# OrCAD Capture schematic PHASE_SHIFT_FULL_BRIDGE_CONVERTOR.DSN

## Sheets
1 PAGE2: size A
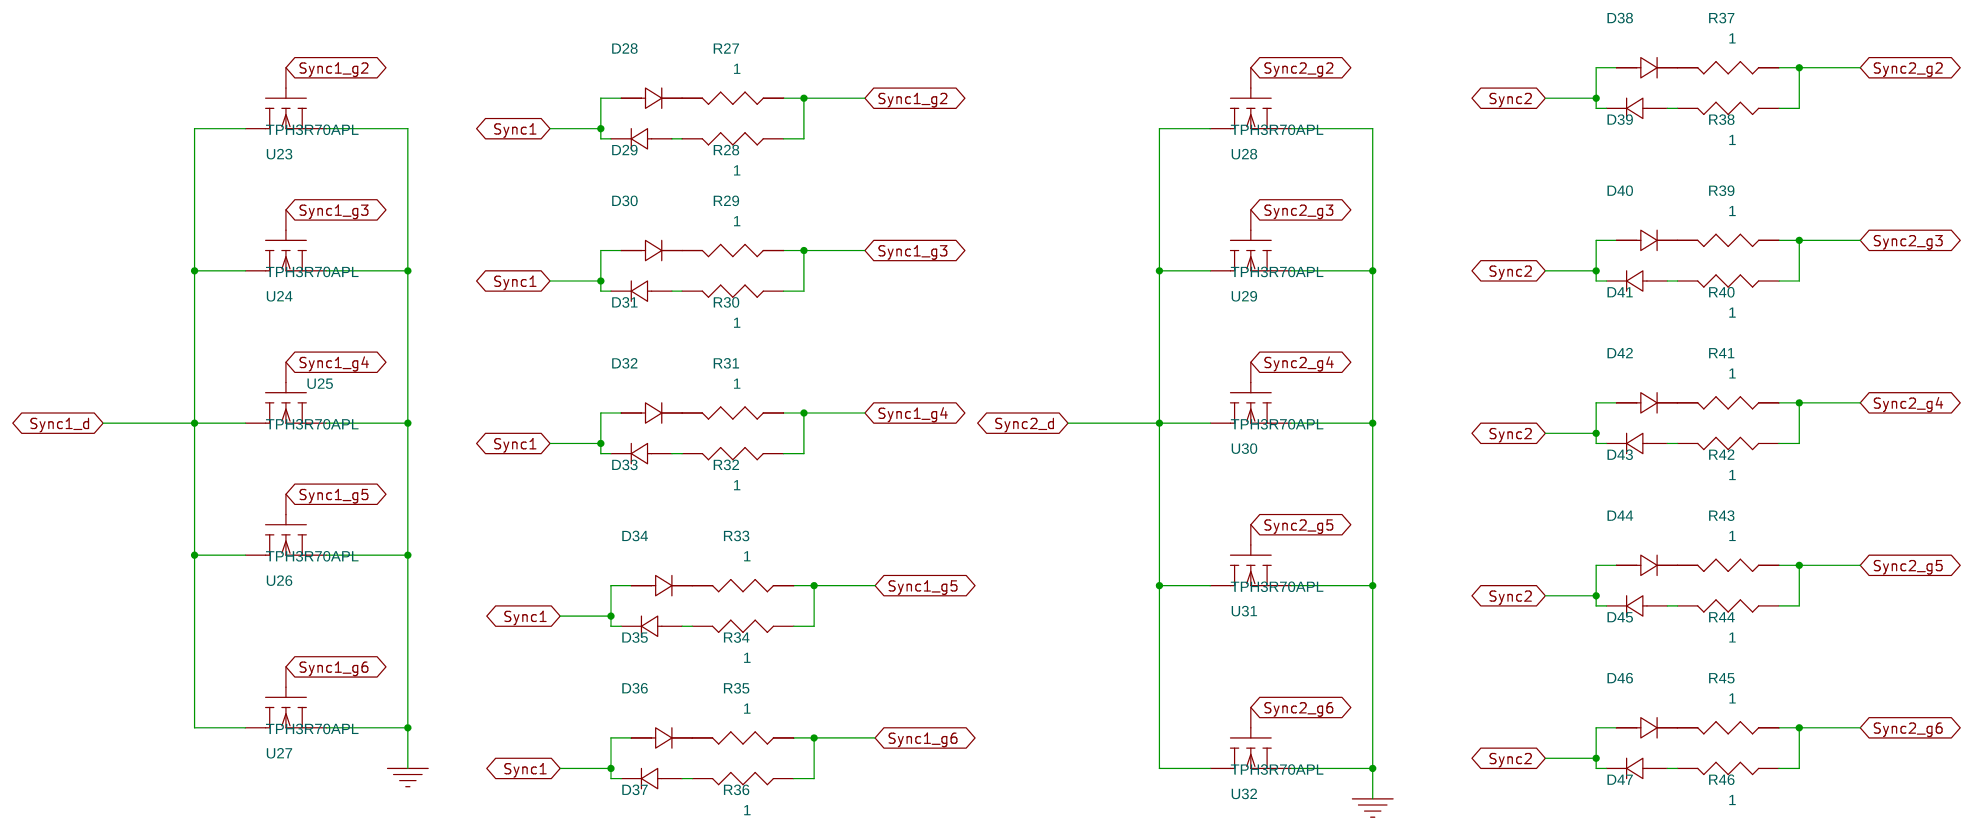
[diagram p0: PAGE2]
2 PAGE1: size A
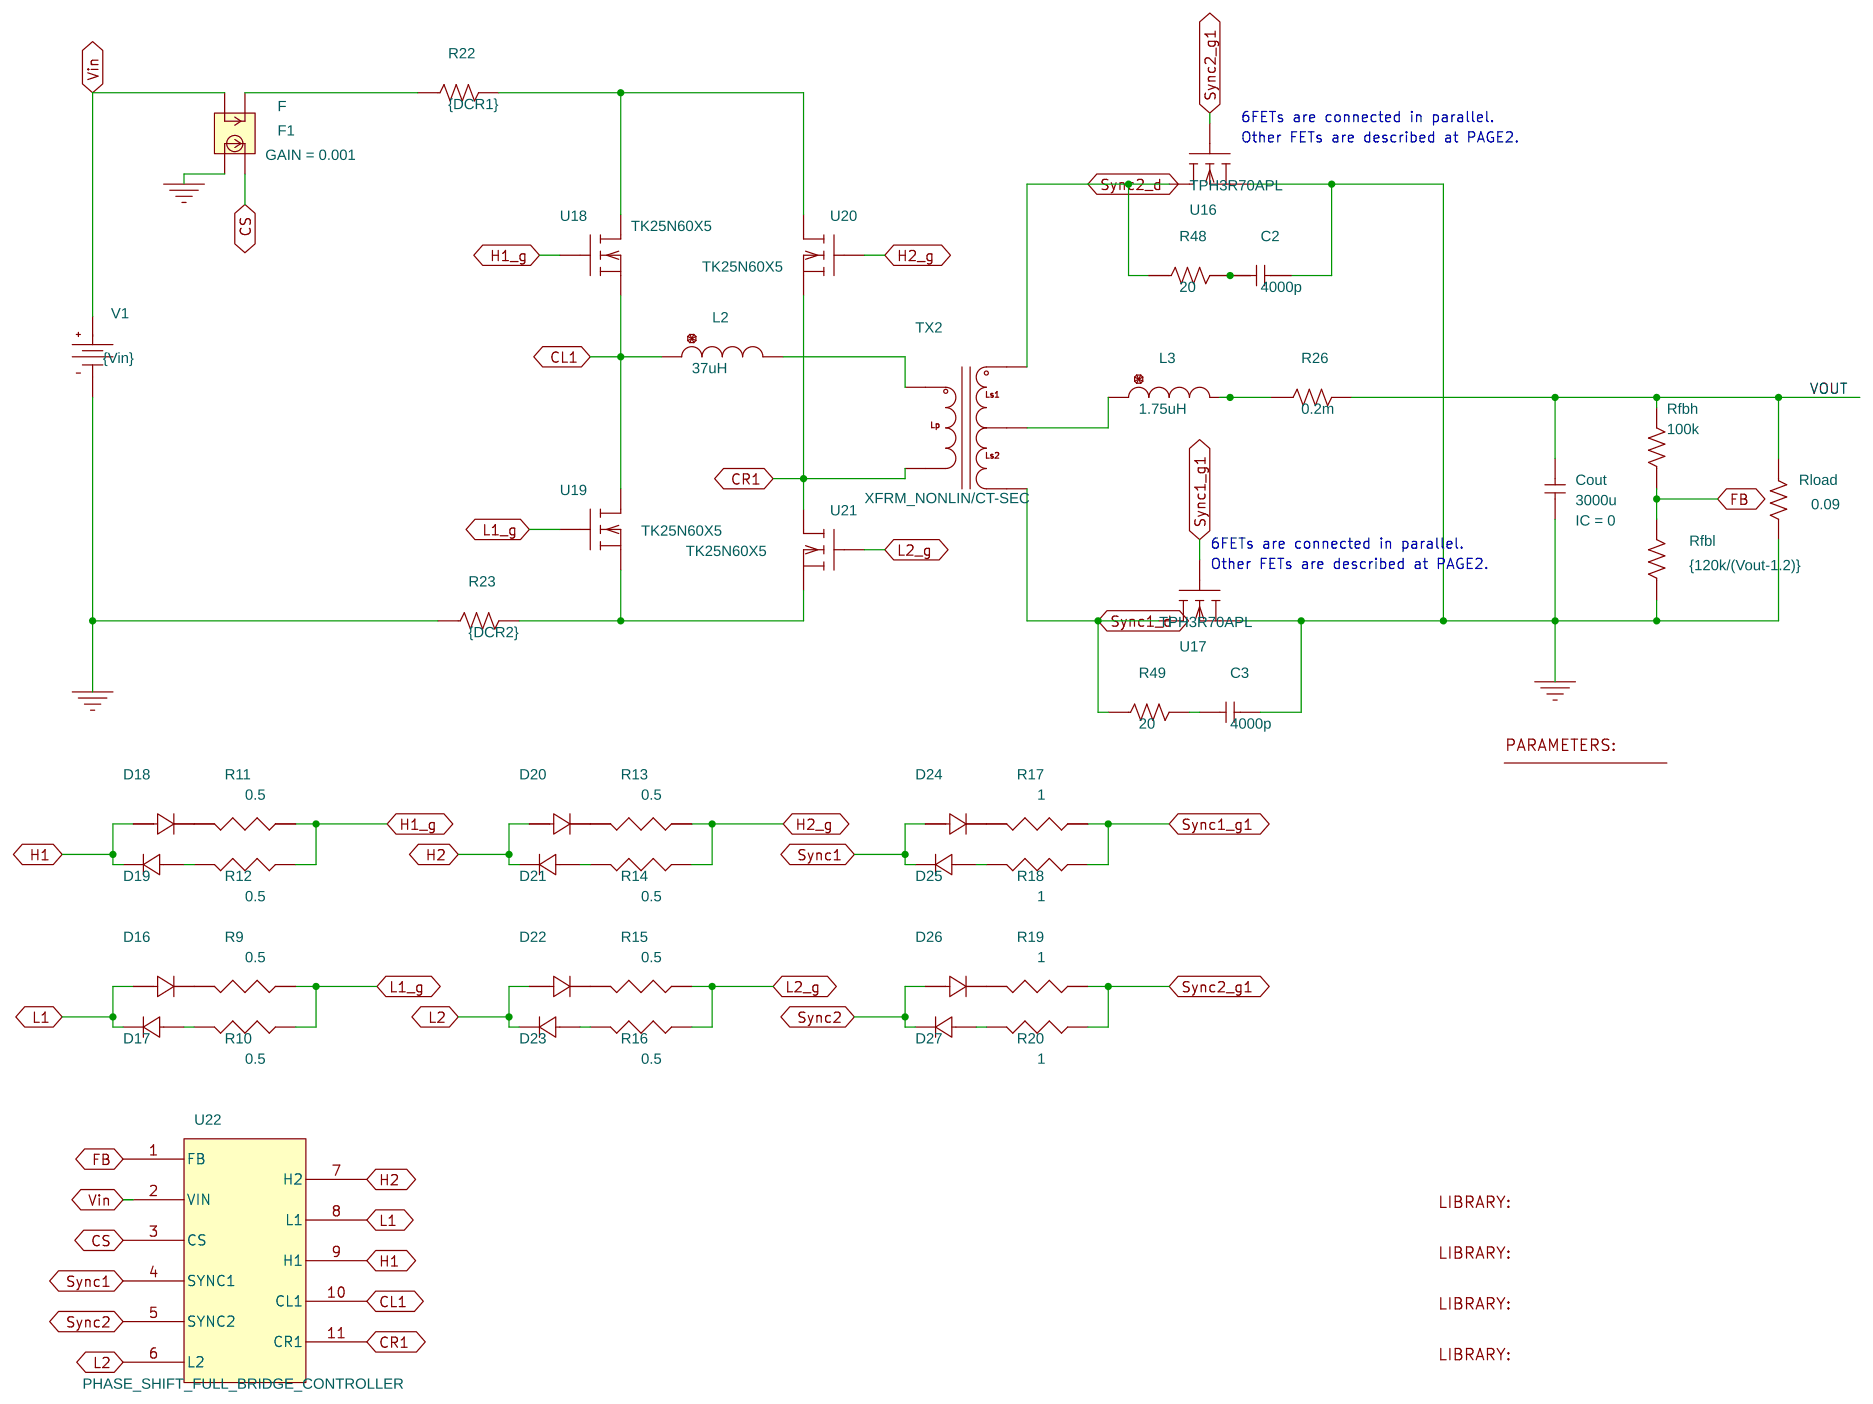
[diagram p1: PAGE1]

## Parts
sheet PAGE1
1  PARAM
C2  4000p  [cap196]
C3  4000p  [cap196]
Cout  3000u  [RAD/CK05]
D16  Diode_nom
D17  Diode_nom
D18  Diode_nom
D19  Diode_nom
D20  Diode_nom
D21  Diode_nom
D22  Diode_nom
D23  Diode_nom
D24  Diode_nom
D25  Diode_nom
D26  Diode_nom
D27  Diode_nom
F1  F
L2  37uH  [DISC350x175LS200x100034]
L3  1.75uH  [DISC350x175LS200x100034]
LIB1  LIB
LIB2  LIB
LIB3  LIB
LIB4  LIB
R9  0.5  [AXRC05]
R10  0.5  [AXRC05]
R11  0.5  [AXRC05]
R12  0.5  [AXRC05]
R13  0.5  [AXRC05]
R14  0.5  [AXRC05]
R15  0.5  [AXRC05]
R16  0.5  [AXRC05]
R17  1  [AXRC05]
R18  1  [AXRC05]
R19  1  [AXRC05]
R20  1  [AXRC05]
R22  {DCR1}  [AXRC05]
R23  {DCR2}  [AXRC05]
R26  0.2m  [AXRC05]
R48  20  [AXRC05]
R49  20  [AXRC05]
Rfbh  100k  [AXRC05]
Rfbl  {120k/(Vout-1.2)}  [AXRC05]
Rload  0.09  [AX/RC05]
TX2  XFRM_NONLIN/CT-SEC
U16  TPH3R70APL
U17  TPH3R70APL
U18  TK25N60X5
U19  TK25N60X5
U20  TK25N60X5
U21  TK25N60X5
U22  PHASE_SHIFT_FULL_BRIDGE_CONTROLLER
V1  VDC
sheet PAGE2
D28  Diode_nom
D29  Diode_nom
D30  Diode_nom
D31  Diode_nom
D32  Diode_nom
D33  Diode_nom
D34  Diode_nom
D35  Diode_nom
D36  Diode_nom
D37  Diode_nom
D38  Diode_nom
D39  Diode_nom
D40  Diode_nom
D41  Diode_nom
D42  Diode_nom
D43  Diode_nom
D44  Diode_nom
D45  Diode_nom
D46  Diode_nom
D47  Diode_nom
R27  1  [AXRC05]
R28  1  [AXRC05]
R29  1  [AXRC05]
R30  1  [AXRC05]
R31  1  [AXRC05]
R32  1  [AXRC05]
R33  1  [AXRC05]
R34  1  [AXRC05]
R35  1  [AXRC05]
R36  1  [AXRC05]
R37  1  [AXRC05]
R38  1  [AXRC05]
R39  1  [AXRC05]
R40  1  [AXRC05]
R41  1  [AXRC05]
R42  1  [AXRC05]
R43  1  [AXRC05]
R44  1  [AXRC05]
R45  1  [AXRC05]
R46  1  [AXRC05]
U23  TPH3R70APL
U24  TPH3R70APL
U25  TPH3R70APL
U26  TPH3R70APL
U27  TPH3R70APL
U28  TPH3R70APL
U29  TPH3R70APL
U30  TPH3R70APL
U31  TPH3R70APL
U32  TPH3R70APL

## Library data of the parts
1 = PARAM: DCR1: 5m; DCR2: 5m; Fc: 120k; Rdrv_off_p: 1.0; Rdrv_off_s: 0.5; Rdrv_on_p: 5.3; Rdrv_on_s: 5; Tdl: 300n; Tdr: 300n; Vdrv_H_p: 12; Vdrv_H_s: 12; Vin: 380; Vout: 12
C2 C3 = C
Cout = C_2: IC: 0
D16-D47 = Diode_nom
F1 = F: GAIN: 0.001
L2 L3 = L
LIB1 = LIB: FILENAME: ../../../Lib/TK25N60X5.lib
LIB2 = LIB: FILENAME: ../../../Lib/TPH3R70APL.lib
LIB3 = LIB: FILENAME: ../../../Lib/diode_nom.lib
LIB4 = LIB: FILENAME: ../../../lib/Phase_shift_controller.lib
R9-R20 R27-R46 = R
R22 R23 R26 R48 R49 Rfbh Rfbl Rload = R_v2
TX2 = XFRM_NONLIN_CT-SEC: COUPLING: 1; LP_TURNS: 400; LS1_TURNS: 20; LS2_TURNS: 20; RP_VALUE: 75e-3; RS_VALUE: 0.25e-3
U16 U17 U23-U32 = TPH3R70APL
U18-U21 = TK25N60X5
U22 = PHASE_SHIFT_FULL_BRIDGE_CONTROL
V1 = VDC: DC: {Vin}

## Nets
Vin: F1.1 U22.2(VIN) V1.0(+)
0: C2.2 C3.2 Cout.2 F1.3 R23.1 Rfbl.1 Rload.2 U16.0(s) U17.0(s) U23.0(s) U24.0(s) U25.0(s) U26.0(s) U27.0(s) U28.0(s) U29.0(s) U30.0(s) U31.0(s) U32.0(s) V1.1(-)
CL1: L2.1 U18.0(s) U19.2(d) U22.10(CL1)
CR1: TX2.1(3) U20.0(s) U21.2(d) U22.11(CR1)
CS: F1.4 U22.3(CS)
FB: Rfbh.1 Rfbl.2 U22.1(FB)
H1: D18.0(1) D19.1(2) U22.9(H1)
H1_g: R11.1 R12.1 U18.1(g)
H2: D20.0(1) D21.1(2) U22.7(H2)
H2_g: R13.1 R14.1 U20.1(g)
L1: D16.0(1) D17.1(2) U22.8(L1)
L1_g: R9.1 R10.1 U19.1(g)
L2: D22.0(1) D23.1(2) U22.6(L2)
L2_g: R15.1 R16.1 U21.1(g)
Sync1: D24.0(1) D25.1(2) D28.0(1) D29.1(2) D30.0(1) D31.1(2) D32.0(1) D33.1(2) D34.0(1) D35.1(2) D36.0(1) D37.1(2) U22.4(SYNC1)
Sync1_d: R49.1 TX2.4(6) U17.2(d) U23.2(d) U24.2(d) U25.2(d) U26.2(d) U27.2(d)
Sync1_g1: R17.1 R18.1 U17.1(g)
Sync1_g2: R27.1 R28.1 U23.1(g)
Sync1_g3: R29.1 R30.1 U24.1(g)
Sync1_g4: R31.1 R32.1 U25.1(g)
Sync1_g5: R33.1 R34.1 U26.1(g)
Sync1_g6: R35.1 R36.1 U27.1(g)
Sync2: D26.0(1) D27.1(2) D38.0(1) D39.1(2) D40.0(1) D41.1(2) D42.0(1) D43.1(2) D44.0(1) D45.1(2) D46.0(1) D47.1(2) U22.5(SYNC2)
Sync2_d: R48.1 TX2.2(4) U16.2(d) U28.2(d) U29.2(d) U30.2(d) U31.2(d) U32.2(d)
Sync2_g1: R19.1 R20.1 U16.1(g)
Sync2_g2: R37.1 R38.1 U28.1(g)
Sync2_g3: R39.1 R40.1 U29.1(g)
Sync2_g4: R41.1 R42.1 U30.1(g)
Sync2_g5: R43.1 R44.1 U31.1(g)
Sync2_g6: R45.1 R46.1 U32.1(g)
VOUT: Cout.1 R26.2 Rfbh.2 Rload.1
N2254419: F1.2 R22.1
N2254423: R22.2 U18.2(d) U20.2(d)
N2254655: L2.2 TX2.0(1)
N2254721: L3.1 TX2.3(5)
N2254725: L3.2 R26.1
N2254961: R23.2 U19.0(s) U21.0(s)
N2255439: D25.0(1) R18.2
N2255467: D19.0(1) R12.2
N2255537: D21.0(1) R14.2
N2255895: D27.0(1) R20.2
N2255923: D17.0(1) R10.2
N2255993: D23.0(1) R16.2
N2258498: D26.1(2) R19.2
N2258518: D20.1(2) R13.2
N2258538: D22.1(2) R15.2
N2258558: D18.1(2) R11.2
N2258582: D16.1(2) R9.2
N2261014: D29.0(1) R28.2
N2261330: D31.0(1) R30.2
N2261652: D33.0(1) R32.2
N2261989: D35.0(1) R34.2
N2262535: D37.0(1) R36.2
N2263556: D39.0(1) R38.2
N2264014: D41.0(1) R40.2
N2264336: D43.0(1) R42.2
N2264671: D45.0(1) R44.2
N2265019: D47.0(1) R46.2
N2269373: D42.1(2) R41.2
N2269374: D40.1(2) R39.2
N2269379: D44.1(2) R43.2
N2269386: D46.1(2) R45.2
N2269388: D38.1(2) R37.2
N2271064: D36.1(2) R35.2
N2271065: D32.1(2) R31.2
N2271066: D34.1(2) R33.2
N2271069: D30.1(2) R29.2
N2271070: D28.1(2) R27.2
N2271124: D24.1(2) R17.2
N2276188: C2.1 R48.2
N2276240: C3.1 R49.2

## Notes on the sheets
sheet 2
- 6FETs are connected in parallel.
- Other FETs are described at PAGE2.
- 6FETs are connected in parallel.
- Other FETs are described at PAGE2.
